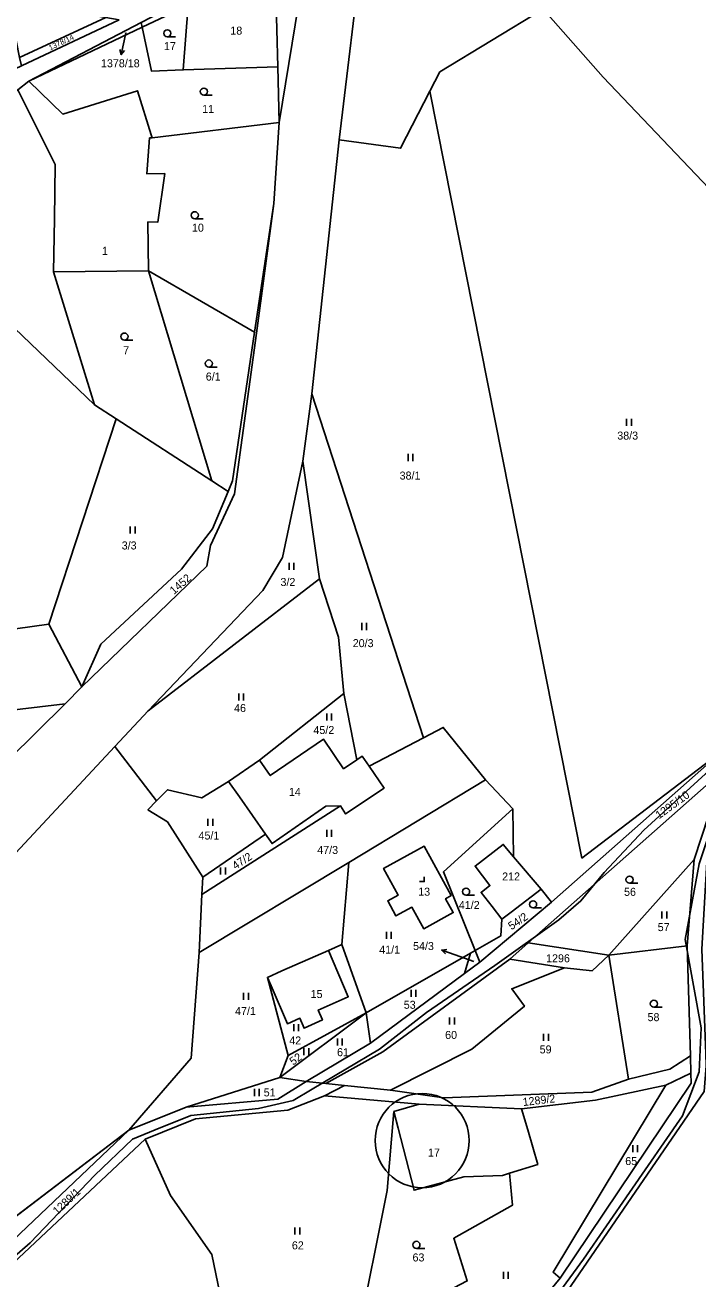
# Model space of a CAD drawing. Extents: x -588699 to -585793, y -1060280 to -1056731.
# Drawn here: x -588343.5 to -588200.6, y -1058381.5 to -1058115.3 of the extents above; entities that cross this region are included whole.
import ezdxf

# ---------------------------------------------------------------- set-up
doc = ezdxf.new("R2010")
doc.units = 0
for name, color, linetype in [('Druh pozemku', 7, 'Continuous'), ('Lesy', 7, 'Continuous'), ('Parcela nároku', 7, 'Continuous'), ('Parcelní číslo', 7, 'Continuous'), ('Stavby', 7, 'Continuous'), ('Vnitřní obvod', 7, 'Continuous')]:
    doc.layers.add(name, color=color, linetype=linetype)

msp = doc.modelspace()

# ---------------------------------------------------------------- linework, layer by layer
at = {"layer": 'Druh pozemku'}
for p, q in [((-588311.57, -1058117.8), (-588313.32, -1058117.8)), ((-588303.81, -1058130.18), (-588305.56, -1058130.18)), ((-588305.73, -1058156.43), (-588307.48, -1058156.43)), ((-588320.67, -1058182.19), (-588322.42, -1058182.19)), ((-588302.75, -1058187.92), (-588304.5, -1058187.92)), ((-588215.77, -1058198.92), (-588215.77, -1058200.42)), ((-588214.74, -1058200.42), (-588214.74, -1058198.92)), ((-588262.16, -1058206.37), (-588262.16, -1058207.87)), ((-588261.14, -1058207.87), (-588261.14, -1058206.37)), ((-588321.19, -1058221.79), (-588321.19, -1058223.29)), ((-588320.17, -1058223.29), (-588320.17, -1058221.79)), ((-588287.43, -1058229.5), (-588287.43, -1058231)), ((-588286.41, -1058231), (-588286.41, -1058229.5)), ((-588272, -1058242.26), (-588272, -1058243.76)), ((-588270.97, -1058243.76), (-588270.97, -1058242.26)), ((-588298.16, -1058257.23), (-588298.16, -1058258.73)), ((-588297.14, -1058258.73), (-588297.14, -1058257.23)), ((-588279.46, -1058261.47), (-588279.46, -1058262.97)), ((-588278.44, -1058262.97), (-588278.44, -1058261.47)), ((-588304.68, -1058283.87), (-588304.68, -1058285.37)), ((-588303.66, -1058285.37), (-588303.66, -1058283.87)), ((-588279.44, -1058286.15), (-588279.44, -1058287.65)), ((-588278.42, -1058287.65), (-588278.42, -1058286.15)), ((-588302, -1058294.17), (-588302, -1058295.67)), ((-588300.97, -1058295.67), (-588300.97, -1058294.17)), ((-588213.38, -1058297.52), (-588215.13, -1058297.52)), ((-588248.09, -1058300.06), (-588249.84, -1058300.06)), ((-588233.86, -1058302.76), (-588235.61, -1058302.76)), ((-588208.26, -1058303.54), (-588208.26, -1058305.04)), ((-588207.23, -1058305.04), (-588207.23, -1058303.54)), ((-588266.77, -1058307.85), (-588266.77, -1058309.35)), ((-588265.74, -1058309.35), (-588265.74, -1058307.85)), ((-588297.11, -1058320.8), (-588297.11, -1058322.3)), ((-588296.08, -1058322.3), (-588296.08, -1058320.8)), ((-588261.53, -1058320.18), (-588261.53, -1058321.68)), ((-588260.51, -1058321.68), (-588260.51, -1058320.18)), ((-588208.21, -1058323.86), (-588209.96, -1058323.86)), ((-588253.35, -1058326.01), (-588253.35, -1058327.51)), ((-588252.33, -1058327.51), (-588252.33, -1058326.01)), ((-588286.46, -1058327.43), (-588286.46, -1058328.93)), ((-588285.44, -1058328.93), (-588285.44, -1058327.43)), ((-588233.39, -1058329.52), (-588233.39, -1058331.02)), ((-588232.36, -1058331.02), (-588232.36, -1058329.52)), ((-588284.31, -1058332.52), (-588284.31, -1058334.02)), ((-588283.29, -1058334.02), (-588283.29, -1058332.52)), ((-588277.16, -1058330.49), (-588277.16, -1058331.99)), ((-588276.14, -1058331.99), (-588276.14, -1058330.49)), ((-588294.81, -1058341.21), (-588294.81, -1058342.71)), ((-588293.79, -1058342.71), (-588293.79, -1058341.21)), ((-588214.44, -1058353.11), (-588214.44, -1058354.61)), ((-588213.42, -1058354.61), (-588213.42, -1058353.11)), ((-588286.2, -1058370.63), (-588286.2, -1058372.13)), ((-588285.18, -1058372.13), (-588285.18, -1058370.63)), ((-588258.64, -1058375.06), (-588260.39, -1058375.06)), ((-588241.9, -1058380.01), (-588241.9, -1058381.51)), ((-588240.88, -1058381.51), (-588240.88, -1058380.01))]:
    msp.add_line(p, q, dxfattribs=at)
msp.add_lwpolyline([(-588259.72, -1058297.18), (-588258.72, -1058297.18), (-588258.72, -1058296.18)], dxfattribs=at)
for centre in [(-588313.32, -1058117.05), (-588305.56, -1058129.43), (-588307.48, -1058155.68), (-588322.42, -1058181.44), (-588304.5, -1058187.17), (-588215.13, -1058296.77), (-588249.84, -1058299.31), (-588235.61, -1058302.01), (-588209.96, -1058323.11), (-588260.39, -1058374.31)]:
    msp.add_circle(centre, 0.75, dxfattribs=at)
at = {"layer": 'Lesy'}
for p, q in [((-588195.07, -1058269.17), (-588231.71, -1058301.52)), ((-588231.71, -1058301.52), (-588246.95, -1058314.3)), ((-588246.95, -1058314.3), (-588250.18, -1058316.69)), ((-588250.18, -1058316.69), (-588270.15, -1058331.48)), ((-588270.15, -1058331.48), (-588283.85, -1058339.62)), ((-588283.85, -1058339.62), (-588289.85, -1058343.41)), ((-588309.35, -1058345.07), (-588321.5, -1058349.96)), ((-588289.85, -1058343.41), (-588309.35, -1058345.07)), ((-588321.5, -1058349.96), (-588382.69, -1058396.58))]:
    msp.add_line(p, q, dxfattribs=at)
at = {"layer": 'Parcela nároku'}
for points in [[(-588347.34, -1058108.72), (-588344.7, -1058122.22), (-588326.35, -1058113.66), (-588334.59, -1058112.33), (-588338.01, -1058106.78), (-588346.56, -1058050.77), (-588355.38, -1058054.63), (-588358.98, -1058080.9), (-588356.77, -1058093.01)], [(-588251.63, -1058089.93), (-588243.9, -1058091.45), (-588233.5, -1058111.89), (-588255.46, -1058125.26), (-588257.55, -1058129.34), (-588263.75, -1058141.47), (-588276.82, -1058139.7), (-588271.78, -1058097.87), (-588261.94, -1058089.86)], [(-588185.34, -1058106.83), (-588243.9, -1058091.45), (-588233.5, -1058111.89), (-588220.72, -1058126.38), (-588187, -1058161.78), (-588151.89, -1058174.08), (-588153.74, -1058161.51), (-588172.49, -1058131.01)], [(-588290.51, -1058100.34), (-588286.65, -1058098.25), (-588283.37, -1058098.3), (-588289.55, -1058135.97), (-588289.87, -1058124.16)], [(-588309.93, -1058124.83), (-588308.87, -1058111.13), (-588303.49, -1058108.58), (-588290.51, -1058100.34), (-588289.87, -1058124.16)], [(-588318.89, -1058114.72), (-588308.74, -1058109.42), (-588308.87, -1058111.13), (-588318.67, -1058115.77)], [(-588308.87, -1058111.13), (-588318.67, -1058115.77), (-588316.7, -1058125.06), (-588309.93, -1058124.83)], [(-588323.52, -1058114.21), (-588326.35, -1058113.66), (-588344.7, -1058122.22), (-588344.31, -1058123.97)], [(-588233.5, -1058111.89), (-588220.72, -1058126.38), (-588187, -1058161.78), (-588186.48, -1058166.56), (-588187.86, -1058166.8), (-588187.14, -1058173.38), (-588195.16, -1058174.34), (-588173.47, -1058255.38), (-588188.13, -1058265.89), (-588195.07, -1058269.17), (-588225.24, -1058292.17), (-588257.55, -1058129.34), (-588255.46, -1058125.26)], [(-588342.77, -1058127.18), (-588318.89, -1058114.72), (-588318.67, -1058115.77)], [(-588309.93, -1058124.83), (-588289.87, -1058124.16), (-588289.55, -1058135.97), (-588316.55, -1058139.21), (-588316.74, -1058138.59), (-588319.63, -1058129.24), (-588335.53, -1058134.21), (-588342.77, -1058127.18), (-588318.67, -1058115.77), (-588316.7, -1058125.06)], [(-588319.63, -1058129.24), (-588335.53, -1058134.21), (-588342.77, -1058127.18), (-588345.06, -1058129.04), (-588337.11, -1058144.94), (-588337.3, -1058156.47), (-588337.48, -1058167.68), (-588317.32, -1058167.52), (-588317.45, -1058157.1), (-588315.37, -1058157.17), (-588313.88, -1058146.84), (-588317.64, -1058146.91), (-588317.1, -1058139.28), (-588316.55, -1058139.21), (-588316.74, -1058138.59)], [(-588352.73, -1058134.94), (-588345.06, -1058129.04), (-588337.11, -1058144.94), (-588337.3, -1058156.47), (-588337.48, -1058167.68), (-588328.8, -1058195.91), (-588354.34, -1058171.49)], [(-588263.75, -1058141.47), (-588276.82, -1058139.7), (-588282.59, -1058193.58), (-588258.92, -1058266.64), (-588254.7, -1058264.42), (-588245.73, -1058275.6), (-588239.91, -1058281.73), (-588239.76, -1058291.89), (-588233.93, -1058298.79), (-588231.71, -1058301.52), (-588195.07, -1058269.17), (-588225.24, -1058292.17), (-588257.55, -1058129.34)], [(-588328.8, -1058195.91), (-588324.16, -1058198.9), (-588338.48, -1058242.51), (-588379.03, -1058248.19), (-588389.52, -1058228.94), (-588372.19, -1058218.57), (-588385.12, -1058191.96), (-588398.8, -1058211.9), (-588412.77, -1058186.25), (-588396.63, -1058177.41), (-588384.28, -1058167.75), (-588377.77, -1058158.52), (-588352.73, -1058134.94), (-588354.34, -1058171.49)], [(-588317.1, -1058139.28), (-588317.64, -1058146.91), (-588313.88, -1058146.84), (-588315.37, -1058157.17), (-588317.45, -1058157.1), (-588317.32, -1058167.52), (-588294.77, -1058180.5), (-588290.72, -1058153.2), (-588289.55, -1058135.97), (-588316.55, -1058139.21)], [(-588303.72, -1058222.25), (-588310.34, -1058230.86), (-588327.42, -1058246.77), (-588331.5, -1058255.79), (-588304.92, -1058230.19), (-588304.15, -1058225.78), (-588299.04, -1058214.85), (-588294.34, -1058180.75), (-588290.72, -1058153.2), (-588294.77, -1058180.5), (-588299.46, -1058212.11), (-588300.39, -1058214.32)], [(-588317.32, -1058167.52), (-588303.85, -1058212.07), (-588324.16, -1058198.9), (-588328.8, -1058195.91), (-588337.48, -1058167.68)], [(-588294.77, -1058180.5), (-588317.32, -1058167.52), (-588303.85, -1058212.07), (-588300.39, -1058214.32), (-588299.46, -1058212.11)], [(-588282.59, -1058193.58), (-588284.53, -1058207.92), (-588281.02, -1058232.87), (-588276.93, -1058245.24), (-588275.84, -1058257.27), (-588273.07, -1058271.33), (-588271.92, -1058270.55), (-588270.45, -1058272.69), (-588258.92, -1058266.64)], [(-588338.48, -1058242.51), (-588324.16, -1058198.9), (-588303.85, -1058212.07), (-588300.39, -1058214.32), (-588303.72, -1058222.25), (-588310.34, -1058230.86), (-588327.42, -1058246.77), (-588331.5, -1058255.79)], [(-588293.04, -1058235.33), (-588288.87, -1058228.37), (-588284.53, -1058207.92), (-588281.02, -1058232.87), (-588317.4, -1058260.9)], [(-588324.47, -1058268.49), (-588317.4, -1058260.9), (-588281.02, -1058232.87), (-588276.93, -1058245.24), (-588275.84, -1058257.27), (-588293.74, -1058271.37), (-588300.33, -1058275.9), (-588305.99, -1058279.42), (-588313.29, -1058277.66), (-588315.59, -1058280.01)], [(-588331.5, -1058255.79), (-588338.48, -1058242.51), (-588379.03, -1058248.19), (-588375.26, -1058255.11), (-588370.39, -1058263.58), (-588335.04, -1058259.4)], [(-588163.19, -1058249.31), (-588159.26, -1058247.68), (-588161.37, -1058254.66), (-588170.17, -1058260.23), (-588188.82, -1058270.29), (-588195.18, -1058273.49), (-588236.69, -1058310.21), (-588240.57, -1058313.64), (-588267.55, -1058333.34), (-588279.64, -1058340.05), (-588283.85, -1058339.62), (-588270.15, -1058331.48), (-588250.18, -1058316.69), (-588246.95, -1058314.3), (-588231.71, -1058301.52), (-588195.07, -1058269.17), (-588188.13, -1058265.89), (-588172.92, -1058257.42), (-588171.55, -1058256.65)], [(-588293.74, -1058271.37), (-588275.84, -1058257.27), (-588273.07, -1058271.33), (-588275.88, -1058273.22), (-588280.15, -1058266.9), (-588291.47, -1058274.68)], [(-588370.39, -1058263.58), (-588335.04, -1058259.4), (-588359.11, -1058283.17)], [(-588276.54, -1058281.11), (-588305.97, -1058299.95), (-588306.58, -1058312.23), (-588274.78, -1058293.09), (-588245.73, -1058275.6), (-588254.7, -1058264.42), (-588258.92, -1058266.64), (-588270.45, -1058272.69), (-588267.26, -1058277.32), (-588275.45, -1058282.8)], [(-588377.16, -1058321.45), (-588387, -1058328.07), (-588422.47, -1058346.26), (-588422.53, -1058349.9), (-588422.74, -1058356.48), (-588422.64, -1058357.02), (-588422.45, -1058358), (-588420.46, -1058368.28), (-588412.96, -1058407.03), (-588382.69, -1058396.58), (-588321.5, -1058349.96), (-588308.25, -1058334.68), (-588306.58, -1058312.23), (-588305.97, -1058299.95), (-588305.79, -1058296.21), (-588313.29, -1058284.5), (-588317.45, -1058281.91), (-588315.59, -1058280.01), (-588324.47, -1058268.49), (-588348.39, -1058294.15)], [(-588280.15, -1058266.9), (-588291.47, -1058274.68), (-588293.74, -1058271.37), (-588300.33, -1058275.9), (-588298.02, -1058279.19), (-588292.49, -1058287.1), (-588291.08, -1058289.12), (-588279.63, -1058281.14), (-588276.54, -1058281.11), (-588275.45, -1058282.8), (-588267.26, -1058277.32), (-588270.45, -1058272.69), (-588271.92, -1058270.55), (-588273.07, -1058271.33), (-588275.88, -1058273.22)], [(-588283.37, -1058455.17), (-588274.9, -1058429.78), (-588264.76, -1058419.13), (-588236.43, -1058389.38), (-588229.89, -1058381.41), (-588202.03, -1058340), (-588202.09, -1058337.86), (-588202.2, -1058334.18), (-588202.91, -1058310.84), (-588201.43, -1058292.5), (-588195.18, -1058273.49), (-588188.82, -1058270.29), (-588198.66, -1058291.81), (-588199.76, -1058311.5), (-588198.93, -1058333.77), (-588198.84, -1058336.33), (-588199.24, -1058341.78), (-588231.84, -1058389.25), (-588271.28, -1058432.34), (-588280.04, -1058457.03), (-588290.75, -1058481.45), (-588298.28, -1058488.56), (-588287.12, -1058463.52)], [(-588236.69, -1058310.21), (-588195.18, -1058273.49), (-588201.43, -1058292.5), (-588219.54, -1058312.83)], [(-588317.45, -1058281.91), (-588315.59, -1058280.01), (-588313.29, -1058277.66), (-588305.99, -1058279.42), (-588300.33, -1058275.9), (-588298.02, -1058279.19), (-588292.49, -1058287.1), (-588305.79, -1058296.21), (-588313.29, -1058284.5)], [(-588254.65, -1058295.11), (-588247.95, -1058311.82), (-588248.89, -1058312.36), (-588271.1, -1058325.04), (-588276.23, -1058310.54), (-588274.78, -1058293.09), (-588245.73, -1058275.6), (-588239.91, -1058281.73)], [(-588291.08, -1058289.12), (-588279.63, -1058281.14), (-588276.54, -1058281.11), (-588305.97, -1058299.95), (-588305.79, -1058296.21), (-588292.49, -1058287.1)], [(-588239.76, -1058291.89), (-588239.91, -1058281.73), (-588254.65, -1058295.11), (-588247.95, -1058311.82), (-588242.48, -1058308.7), (-588242.26, -1058305.17), (-588244.3, -1058302.48), (-588246.66, -1058299.46), (-588244.77, -1058298.01), (-588247.95, -1058293.88), (-588241.96, -1058289.28)], [(-588267.38, -1058294.36), (-588258.78, -1058289.65), (-588253.02, -1058300.16), (-588254.2, -1058300.81), (-588252.59, -1058303.74), (-588258.84, -1058307.18), (-588261.37, -1058302.63), (-588264.74, -1058304.47), (-588266.5, -1058301.26), (-588264.28, -1058300.06)], [(-588258.84, -1058307.18), (-588261.37, -1058302.63), (-588264.74, -1058304.47), (-588266.5, -1058301.26), (-588264.28, -1058300.06), (-588267.38, -1058294.36), (-588258.78, -1058289.65), (-588253.02, -1058300.16), (-588254.2, -1058300.81), (-588252.59, -1058303.74)], [(-588241.96, -1058289.28), (-588247.95, -1058293.88), (-588244.77, -1058298.01), (-588246.66, -1058299.46), (-588244.3, -1058302.48), (-588242.26, -1058305.17), (-588240.26, -1058303.7), (-588233.93, -1058298.79), (-588239.76, -1058291.89)], [(-588201.43, -1058292.5), (-588219.54, -1058312.83), (-588202.91, -1058310.84)], [(-588308.25, -1058334.68), (-588306.58, -1058312.23), (-588274.78, -1058293.09), (-588276.23, -1058310.54), (-588279.09, -1058311.8), (-588288.99, -1058316.16), (-588292.07, -1058317.52), (-588287.63, -1058334.07), (-588289.39, -1058338.78), (-588309.35, -1058345.07), (-588321.5, -1058349.96)], [(-588247.95, -1058311.82), (-588242.48, -1058308.7), (-588242.26, -1058305.17), (-588240.26, -1058303.7), (-588233.93, -1058298.79), (-588231.71, -1058301.52), (-588246.95, -1058314.3)], [(-588280.36, -1058326.55), (-588284.27, -1058328.3), (-588285.16, -1058326.18), (-588287.8, -1058327.37), (-588291.29, -1058319.31), (-588292.07, -1058317.52), (-588287.63, -1058334.07), (-588271.1, -1058325.04), (-588276.23, -1058310.54), (-588279.09, -1058311.8), (-588274.87, -1058321.64), (-588281.24, -1058324.46)], [(-588240.57, -1058313.64), (-588236.69, -1058310.21), (-588219.54, -1058312.83), (-588223.08, -1058316.1), (-588228.97, -1058315.5)], [(-588219.54, -1058312.83), (-588202.91, -1058310.84), (-588202.2, -1058334.18), (-588206.57, -1058336.98), (-588215.33, -1058339.13)], [(-588281.24, -1058324.46), (-588280.36, -1058326.55), (-588284.27, -1058328.3), (-588285.16, -1058326.18), (-588287.8, -1058327.37), (-588291.29, -1058319.31), (-588292.07, -1058317.52), (-588288.99, -1058316.16), (-588279.09, -1058311.8), (-588274.87, -1058321.64)], [(-588267.55, -1058333.34), (-588279.64, -1058340.05), (-588275.7, -1058340.46), (-588265.93, -1058341.47), (-588248.65, -1058332.78), (-588237.47, -1058323.63), (-588240.15, -1058319.93), (-588228.97, -1058315.5), (-588240.57, -1058313.64)], [(-588271.1, -1058325.04), (-588248.89, -1058312.36), (-588250.18, -1058316.69), (-588270.15, -1058331.48)], [(-588219.54, -1058312.83), (-588215.33, -1058339.13), (-588223.1, -1058341.89), (-588254.61, -1058343.11), (-588265.93, -1058341.47), (-588248.65, -1058332.78), (-588237.47, -1058323.63), (-588240.15, -1058319.93), (-588228.97, -1058315.5), (-588223.08, -1058316.1)], [(-588250.18, -1058316.69), (-588248.89, -1058312.36), (-588247.95, -1058311.82), (-588246.95, -1058314.3)], [(-588287.63, -1058334.07), (-588271.1, -1058325.04), (-588289.39, -1058338.78)], [(-588271.1, -1058325.04), (-588289.39, -1058338.78), (-588283.85, -1058339.62), (-588270.15, -1058331.48)], [(-588199.24, -1058341.78), (-588198.84, -1058336.33), (-588190.26, -1058332.87), (-588165.06, -1058384.36), (-588204.14, -1058407.47), (-588207.77, -1058386.34), (-588227.9, -1058405.85), (-588280.04, -1058457.03), (-588271.28, -1058432.34), (-588231.84, -1058389.25)], [(-588265.93, -1058341.47), (-588254.61, -1058343.11), (-588223.1, -1058341.89), (-588215.33, -1058339.13), (-588206.57, -1058336.98), (-588202.2, -1058334.18), (-588202.09, -1058337.86), (-588207.43, -1058340.37), (-588222.35, -1058343.56), (-588238.08, -1058345.41), (-588259.83, -1058344.41), (-588279.96, -1058342.65), (-588275.7, -1058340.46)], [(-588202.03, -1058340), (-588202.09, -1058337.86), (-588207.43, -1058340.37), (-588231.36, -1058380.12), (-588229.89, -1058381.41)], [(-588411.37, -1058415.27), (-588411.88, -1058412.63), (-588390.19, -1058405.75), (-588373.47, -1058394.95), (-588356.3, -1058382.96), (-588321.5, -1058349.96), (-588309.35, -1058345.07), (-588289.85, -1058343.41), (-588283.85, -1058339.62), (-588279.64, -1058340.05), (-588275.7, -1058340.46), (-588279.96, -1058342.65), (-588287.72, -1058345.7), (-588307.31, -1058347.54), (-588318.03, -1058351.89), (-588353.16, -1058384.75), (-588390.75, -1058409.05)], [(-588289.39, -1058338.78), (-588309.35, -1058345.07), (-588289.85, -1058343.41), (-588283.85, -1058339.62)], [(-588252.48, -1058372.92), (-588240.01, -1058365.89), (-588240.63, -1058359.1), (-588234.62, -1058357.27), (-588236.71, -1058349.89), (-588238.08, -1058345.41), (-588222.35, -1058343.56), (-588207.43, -1058340.37), (-588231.36, -1058380.12), (-588229.89, -1058381.41), (-588236.43, -1058389.38), (-588264.76, -1058419.13), (-588272.95, -1058394.2), (-588249.61, -1058381.97)], [(-588318.03, -1058351.89), (-588307.31, -1058347.54), (-588287.72, -1058345.7), (-588279.96, -1058342.65), (-588259.83, -1058344.41), (-588265.17, -1058346), (-588266.58, -1058362.77), (-588272.95, -1058394.2), (-588299.09, -1058399.3), (-588303.89, -1058376.38), (-588312.67, -1058363.81)], [(-588265.17, -1058346), (-588259.83, -1058344.41), (-588238.08, -1058345.41), (-588236.71, -1058349.89), (-588234.62, -1058357.27), (-588240.63, -1058359.1), (-588242.14, -1058359.56), (-588250.36, -1058359.85), (-588260.9, -1058362.71), (-588264.27, -1058349.53)], [(-588240.63, -1058359.1), (-588242.14, -1058359.56), (-588250.36, -1058359.85), (-588260.9, -1058362.71), (-588264.27, -1058349.53), (-588265.17, -1058346), (-588266.58, -1058362.77), (-588272.95, -1058394.2), (-588249.61, -1058381.97), (-588252.48, -1058372.92), (-588240.01, -1058365.89)], [(-588393.35, -1058404.86), (-588382.69, -1058396.58), (-588321.5, -1058349.96), (-588356.3, -1058382.96), (-588373.47, -1058394.95), (-588390.19, -1058405.75), (-588411.88, -1058412.63), (-588412.18, -1058411.08)], [(-588411.37, -1058415.27), (-588390.75, -1058409.05), (-588353.16, -1058384.75), (-588318.03, -1058351.89), (-588312.67, -1058363.81), (-588303.89, -1058376.38), (-588299.09, -1058399.3), (-588300.31, -1058407.3), (-588314.7, -1058437.22), (-588311.14, -1058455.01), (-588355.77, -1058477.5), (-588376.46, -1058483.16), (-588388.17, -1058472.04), (-588382.47, -1058463.49), (-588389.54, -1058443.73), (-588396.44, -1058454.3), (-588401.78, -1058438.01)]]:
    msp.add_lwpolyline(points, close=True, dxfattribs=at)
for points in [[(-588271.78, -1058097.87), (-588276.82, -1058139.7), (-588282.59, -1058193.58), (-588284.53, -1058207.92), (-588288.87, -1058228.37), (-588293.04, -1058235.33), (-588317.4, -1058260.9), (-588324.47, -1058268.49), (-588348.39, -1058294.15)], [(-588359.11, -1058283.17), (-588335.04, -1058259.4), (-588331.5, -1058255.79), (-588304.92, -1058230.19), (-588304.15, -1058225.78), (-588299.04, -1058214.85), (-588294.34, -1058180.75), (-588290.72, -1058153.2), (-588289.55, -1058135.97), (-588283.37, -1058098.3)], [(-588318.89, -1058114.72), (-588342.77, -1058127.18), (-588345.06, -1058129.04), (-588364.6, -1058142.1), (-588377.77, -1058158.52), (-588389.11, -1058169.67), (-588412.77, -1058186.25), (-588422.39, -1058189.41), (-588434.97, -1058191.08), (-588435.25, -1058189.88), (-588420.67, -1058183.06), (-588399.71, -1058172.63), (-588390.93, -1058165.33), (-588380.84, -1058152.03), (-588365.65, -1058138.16), (-588346.99, -1058125.2), (-588344.31, -1058123.97), (-588323.52, -1058114.21)]]:
    msp.add_lwpolyline(points, dxfattribs=at)
at = {"layer": 'Parcelní číslo'}
for p, q in [((-588322.51, -1058118.62), (-588323.12, -1058121.56)), ((-588322.16, -1058116.96), (-588322.51, -1058118.62)), ((-588252.2, -1058312.72), (-588255.03, -1058311.71)), ((-588248.22, -1058314.14), (-588252.2, -1058312.72))]:
    msp.add_line(p, q, dxfattribs=at)
for points in [[(-588322.43, -1058120.68), (-588323.12, -1058121.56), (-588323.41, -1058120.48)], [(-588254.25, -1058312.52), (-588255.03, -1058311.71), (-588253.92, -1058311.58)]]:
    msp.add_lwpolyline(points, dxfattribs=at)
at = {"layer": 'Stavby'}
msp.add_circle((-588259.18, -1058352.18), 10, dxfattribs=at)
at = {"layer": 'Vnitřní obvod'}
for points in [[(-588191.94, -1058269.73), (-588198.97, -1058274.28), (-588212.08, -1058286.24), (-588220.48, -1058295.28), (-588225.45, -1058301.27), (-588230.18, -1058305.31), (-588243.74, -1058314.96), (-588258.25, -1058324.96), (-588268.22, -1058332.75), (-588282.52, -1058341.26), (-588286.56, -1058343.66), (-588293.95, -1058345.35), (-588308.3, -1058346.81), (-588315.88, -1058349.9), (-588320.71, -1058351.87), (-588328.74, -1058359.49), (-588342.46, -1058373.88), (-588354.02, -1058383.85), (-588368.24, -1058393.93), (-588378.63, -1058400.49), (-588387.38, -1058405.6), (-588393.78, -1058408.34), (-588411.62, -1058413.95)], [(-588232.82, -1058388.18), (-588224.91, -1058377.38), (-588215.1, -1058363.19), (-588203.84, -1058346.9), (-588200.31, -1058337.56), (-588199.93, -1058328.2), (-588203.28, -1058309.5), (-588200.35, -1058293.4), (-588195.33, -1058278.28), (-588191.94, -1058269.73)]]:
    msp.add_lwpolyline(points, dxfattribs=at)

# ---------------------------------------------------------------- texts
at = {"layer": 'Parcela nároku'}
for s, height, p in [('1378/18', 0.1, (-588322.38, -1058116.96)), ('18', 1.7, (-588299.93, -1058117.33)), ('17', 1.7, (-588314.03, -1058120.62)), ('11', 1.7, (-588305.92, -1058133.96)), ('10', 1.7, (-588308.08, -1058159.17)), ('1', 1.7, (-588327.2, -1058164.09)), ('7', 1.7, (-588322.7, -1058185.2)), ('6/1', 1.7, (-588305.15, -1058190.79)), ('38/3', 1.7, (-588217.73, -1058203.32)), ('38/1', 1.7, (-588263.97, -1058211.81)), ('3/3', 1.7, (-588323.01, -1058226.65)), ('3/2', 1.7, (-588289.28, -1058234.41)), ('20/3', 1.7, (-588273.93, -1058247.39)), ('46', 1.7, (-588299.14, -1058261.17)), ('45/2', 1.7, (-588282.28, -1058265.84)), ('14', 1.7, (-588287.49, -1058278.97)), ('45/1', 1.7, (-588306.69, -1058288.24)), ('47/3', 1.7, (-588281.47, -1058291.31)), ('212', 1.7, (-588242.19, -1058296.94)), ('13', 1.7, (-588260.02, -1058300.17)), ('56', 1.7, (-588216.29, -1058300.2)), ('41/2', 1.7, (-588251.39, -1058303)), ('57', 1.7, (-588209.14, -1058307.69)), ('41/1', 1.7, (-588268.3, -1058312.48)), ('1296', 1.7, (-588232.85, -1058314.31)), ('54/3', 0.1, (-588248.37, -1058314.14)), ('15', 1.7, (-588282.88, -1058321.9)), ('47/1', 1.7, (-588298.93, -1058325.5)), ('53', 1.7, (-588263.09, -1058324.18)), ('58', 1.7, (-588211.3, -1058326.81)), ('60', 1.7, (-588254.3, -1058330.59)), ('42', 1.7, (-588287.41, -1058331.76)), ('61', 1.7, (-588277.26, -1058334.25)), ('59', 1.7, (-588234.22, -1058333.66)), ('51', 1.7, (-588292.84, -1058342.79)), ('17', 1.7, (-588257.94, -1058355.57)), ('65', 1.7, (-588216.04, -1058357.37)), ('62', 1.7, (-588286.86, -1058375.27)), ('63', 1.7, (-588261.23, -1058377.83))]:
    msp.add_text(s, height=height, dxfattribs=at).set_placement(p)
for s, height, rotation, p in [('1378/14', 1.14, 25.2778, (-588338.19, -1058120.7)), ('1452', 1.7, 41.0597, (-588311.9, -1058236.3)), ('1295/10', 1.7, 35.8195, (-588208.85, -1058283.95)), ('47/2', 1.7, 32.908, (-588298.85, -1058294.7)), ('54/2', 1.7, 34.1546, (-588240.2, -1058307.53)), ('52', 1.7, 35.623, (-588286.6, -1058336.27)), ('1289/2', 1.7, 6.7077, (-588237.72, -1058344.85)), ('1289/1', 1.7, 43.0878, (-588336.7, -1058368.04))]:
    msp.add_text(s, height=height, rotation=rotation, dxfattribs=at).set_placement(p)
at = {"layer": 'Parcelní číslo'}
for s, p in [('1378/18', (-588327.41, -1058124.26)), ('54/3', (-588261.11, -1058311.71))]:
    msp.add_text(s, height=1.7, dxfattribs=at).set_placement(p)

doc.saveas('drawing.dxf')
